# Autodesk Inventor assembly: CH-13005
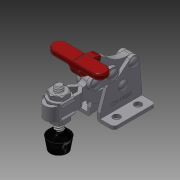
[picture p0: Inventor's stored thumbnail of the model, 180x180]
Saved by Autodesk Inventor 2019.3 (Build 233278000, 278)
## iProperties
Company: Î¢ÈíÖÐ¹ú
Created: 2012-09
Part Number: CH-13005
Material: Ogólny
Description: STEP AP203
Document SubType Name: Assembly
Designer: CADENGINEERING4
Stock Number: DOCISK PIONOWY
Sending System: SolidWorks 2010
Preprocessor: SwSTEP 2.0
Title: CH-13005.STEP
Author: Î¢ÈíÓÃ»§
Revision Number: ÈÎºÎ
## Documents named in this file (9)
- D:\Vault_2016\Projekty\Clamptek\STRONA\Vertical toggle clamp\CH-13005\CH-13005.iam
- D:\Vault_2016\Projekty\Clamptek\STRONA\Vertical toggle clamp\CH-13005\CH-13005-04 CONNECTING-PLATE.ipt
- D:\Vault_2016\Projekty\Clamptek\STRONA\Vertical toggle clamp\CH-13005\CH-13005-03 T-HANDLE.ipt
- D:\Vault_2016\Projekty\Clamptek\STRONA\Vertical toggle clamp\CH-13005\CH-13005-01 FLANGED BASE.ipt
- D:\Vault_2016\Projekty\Clamptek\STRONA\Vertical toggle clamp\CH-13005\CH-13005-02 U-BAR.ipt
- D:\Vault_2016\Projekty\Clamptek\STRONA\Vertical toggle clamp\CH-13005\CH-FW-100.ipt
- D:\Vault_2016\Projekty\Clamptek\STRONA\Vertical toggle clamp\CH-13005\CH-13005-05 .ipt
- D:\Vault_2016\Projekty\Clamptek\STRONA\Vertical toggle clamp\CH-13005\CH-FC-10138 SPINDLE SUPPLIED.ipt
- D:\Vault_2016\Projekty\Clamptek\STRONA\Vertical toggle clamp\CH-13005\CH-FC-10138 Nut.ipt
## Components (14 placed, 14 different names)
1. CH-13005-04 CONNECTING-PLATE_1 — Zestawiające:5, Zestawiające:6, Zestawiające:10, Zestawiające:17, Zestawiające:18
2. CH-13005-03 T-HANDLE_2 — Zestawiające:2, Zestawiające:3, Zestawiające:6, Zestawiające:8
3. CH-13005-01 FLANGED BASE_3 — Zestawiające:1, Zestawiające:2, Zestawiające:7, Zestawiające:8, Zestawiające:11, Zestawiające:12, Zestawiające:13, Zestawiające:14, Zestawiające:19
4. CH-13005-02 U-BAR_4 — Zestawiające:1, Zestawiające:4, Zestawiające:5, Zestawiające:7, Zestawiające:9, Zestawiające:10, Zestawiające:21, Zestawiające:22, Zestawiające:23, Zestawiające:24, Kątowe:1, Kątowe:2
5. CH-13005-04 CONNECTING-PLATE_5 — Zestawiające:3, Zestawiające:4, Zestawiające:9, Zestawiające:15, Zestawiające:16, Zestawiające:19
6. CH-FW-100_6 — Zestawiające:20, Zestawiające:21, Zestawiające:23, Zestawiające:24, Zestawiające:26, Zestawiające:27, Kątowe:1
7. CH-13005-05 _7 — Zestawiające:12, Zestawiające:13
8. CH-FC-10138 SPINDLE SUPPLIED_8 — Zestawiające:29, Równoległe:1
9. CH-13005-05 _9 — Zestawiające:16, Zestawiające:18
10. CH-13005-05 _10 — Zestawiające:15, Zestawiające:17
11. CH-13005-05 _11 — Zestawiające:11, Zestawiające:14
12. CH-FC-10138 Nut_12 — Zestawiające:26, Zestawiające:27
13. CH-FW-100_13 — Zestawiające:20, Zestawiające:22, Zestawiające:25, Zestawiające:28, Równoległe:1, Kątowe:2
14. CH-FC-10138 Nut_14 — Zestawiające:25, Zestawiające:28, Zestawiające:29
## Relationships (32: Mate 29, Angle 2, Flush 1)
- Zestawiające:1 [Mate]: CH-13005-01 FLANGED BASE_3 ↔ CH-13005-02 U-BAR_4
- Zestawiające:2 [Mate]: CH-13005-03 T-HANDLE_2 ↔ CH-13005-01 FLANGED BASE_3
- Zestawiające:3 [Mate]: CH-13005-03 T-HANDLE_2 ↔ CH-13005-04 CONNECTING-PLATE_5
- Zestawiające:4 [Mate]: CH-13005-02 U-BAR_4 ↔ CH-13005-04 CONNECTING-PLATE_5
- Zestawiające:5 [Mate]: CH-13005-04 CONNECTING-PLATE_1 ↔ CH-13005-02 U-BAR_4
- Zestawiające:6 [Mate]: CH-13005-04 CONNECTING-PLATE_1 ↔ CH-13005-03 T-HANDLE_2
- Zestawiające:7 [Mate]: CH-13005-01 FLANGED BASE_3 ↔ CH-13005-02 U-BAR_4
- Zestawiające:8 [Mate]: CH-13005-03 T-HANDLE_2 ↔ CH-13005-01 FLANGED BASE_3
- Zestawiające:9 [Mate]: CH-13005-02 U-BAR_4 ↔ CH-13005-04 CONNECTING-PLATE_5
- Zestawiające:10 [Mate]: CH-13005-04 CONNECTING-PLATE_1 ↔ CH-13005-02 U-BAR_4
- Zestawiające:11 [Mate]: CH-13005-01 FLANGED BASE_3 ↔ CH-13005-05 _11
- Zestawiające:12 [Mate]: CH-13005-01 FLANGED BASE_3 ↔ CH-13005-05 _7
- Zestawiające:13 [Mate]: CH-13005-01 FLANGED BASE_3 ↔ CH-13005-05 _7
- Zestawiające:14 [Mate]: CH-13005-01 FLANGED BASE_3 ↔ CH-13005-05 _11
- Zestawiające:15 [Mate]: CH-13005-04 CONNECTING-PLATE_5 ↔ CH-13005-05 _10
- Zestawiające:16 [Mate]: CH-13005-04 CONNECTING-PLATE_5 ↔ CH-13005-05 _9
- Zestawiające:17 [Mate]: CH-13005-04 CONNECTING-PLATE_1 ↔ CH-13005-05 _10
- Zestawiające:18 [Mate]: CH-13005-04 CONNECTING-PLATE_1 ↔ CH-13005-05 _9
- Zestawiające:19 [Mate]: CH-13005-01 FLANGED BASE_3 ↔ CH-13005-04 CONNECTING-PLATE_5
- Zestawiające:20 [Mate]: CH-FW-100_6 ↔ CH-FW-100_13
- Zestawiające:21 [Mate]: CH-13005-02 U-BAR_4 ↔ CH-FW-100_6
- Zestawiające:22 [Mate]: CH-13005-02 U-BAR_4 ↔ CH-FW-100_13
- Zestawiające:23 [Mate]: CH-13005-02 U-BAR_4 ↔ CH-FW-100_6
- Zestawiające:24 [Mate]: CH-13005-02 U-BAR_4 ↔ CH-FW-100_6
- Zestawiające:25 [Mate]: CH-FW-100_13 ↔ CH-FC-10138 Nut_14
- Zestawiające:26 [Mate]: CH-FW-100_6 ↔ CH-FC-10138 Nut_12
- Zestawiające:27 [Mate]: CH-FW-100_6 ↔ CH-FC-10138 Nut_12
- Zestawiające:28 [Mate]: CH-FW-100_13 ↔ CH-FC-10138 Nut_14
- Zestawiające:29 [Mate]: CH-FC-10138 SPINDLE SUPPLIED_8 ↔ CH-FC-10138 Nut_14
- Równoległe:1 [Flush]: CH-FC-10138 SPINDLE SUPPLIED_8 ↔ CH-FW-100_13
- Kątowe:1 [Angle]: CH-13005-02 U-BAR_4 ↔ CH-FW-100_6
- Kątowe:2 [Angle]: CH-13005-02 U-BAR_4 ↔ CH-FW-100_13
